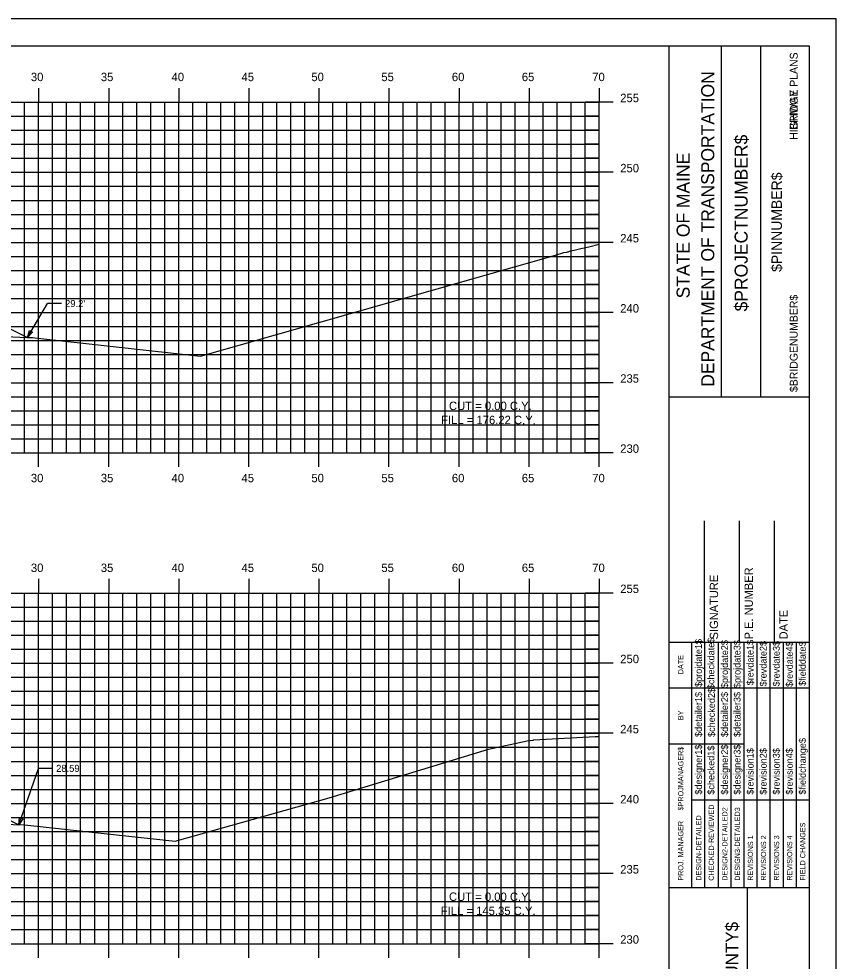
# Model space of a CAD drawing. Extents: x 1160718 to 1173142, y 616002 to 617630.
# Drawn here: x 1168216.9 to 1168275.2, y 616656.7 to 616723.9 of the extents above; entities that cross this region are included whole.
import ezdxf

# ---------------------------------------------------------------- set-up
doc = ezdxf.new("R2010")
doc.units = 0
for name, color, linetype in [('ANNOTATION', 7, 'Continuous'), ('BORDER', 7, 'Continuous'), ('BRIDGE_TITLE', 7, 'Continuous'), ('D_Roadway_SlopeLines', 7, 'Continuous'), ('H_V ANNOTATION', 7, 'Continuous'), ('HIGHWAY_TITLE', 7, 'Continuous'), ('MAJOR', 7, 'Continuous'), ('MINOR', 7, 'Continuous'), ('PLOT BOUNDARY', 7, 'Continuous'), ('S_Roadway_Centerline', 7, 'Continuous')]:
    doc.layers.add(name, color=color, linetype=linetype)

msp = doc.modelspace()

# ---------------------------------------------------------------- linework, layer by layer
at = {"layer": 'ANNOTATION'}
for p, q in [((1168217.545, 616701.158), (1168218.981, 616703.57)), ((1168219.981, 616703.57), (1168218.981, 616703.57)), ((1168216.931, 616666.408), (1168218.342, 616670.428)), ((1168219.342, 616670.428), (1168218.342, 616670.428))]:
    msp.add_line(p, q, dxfattribs=at)
for points in [[(1168217.908, 616701.523), (1168217.545, 616701.158), (1168217.694, 616701.651)], [(1168217.214, 616666.839), (1168216.931, 616666.408), (1168216.978, 616666.921)]]:
    msp.add_lwpolyline(points, close=True, dxfattribs=at)
at = {"layer": 'BORDER'}
for p, q in [((1168273.342, 616721.928), (1168113.342, 616721.928)), ((1168263.342, 616616.931), (1168263.342, 616721.931)), ((1168267.07, 616696.925), (1168267.07, 616721.925)), ((1168269.865, 616696.925), (1168269.865, 616721.925)), ((1168273.342, 616616.931), (1168273.342, 616721.931)), ((1168263.343, 616696.923), (1168273.342, 616696.923)), ((1168265.842, 616679.431), (1168265.842, 616688.079)), ((1168268.342, 616679.431), (1168268.342, 616688.079)), ((1168270.842, 616679.431), (1168270.842, 616688.079)), ((1168263.342, 616679.431), (1168273.342, 616679.431)), ((1168263.342, 616661.931), (1168273.342, 616661.931)), ((1168268.933, 616626.931), (1168268.933, 616661.931))]:
    msp.add_line(p, q, dxfattribs=at)
for points in [[(1168264.957, 616676.181), (1168264.957, 616679.431)], [(1168265.889, 616661.934), (1168265.889, 616679.431)], [(1168266.821, 616679.431), (1168266.821, 616661.934)], [(1168267.753, 616661.934), (1168267.753, 616679.431)], [(1168268.684, 616661.934), (1168268.684, 616679.431)], [(1168269.616, 616661.934), (1168269.616, 616679.431)], [(1168270.548, 616661.934), (1168270.548, 616679.431)], [(1168271.479, 616661.934), (1168271.479, 616679.431)], [(1168272.411, 616661.934), (1168272.411, 616679.431)], [(1168264.958, 616661.934), (1168264.958, 616678.725)], [(1168263.342, 616676.181), (1168273.342, 616676.181)], [(1168263.342, 616672.181), (1168264.958, 616672.181)], [(1168264.957, 616672.181), (1168268.683, 616672.181)], [(1168264.957, 616668.181), (1168273.342, 616668.181)]]:
    msp.add_lwpolyline(points, dxfattribs=at)
at = {"layer": 'D_Roadway_SlopeLines'}
for points in [[(1168208.342, 616705.76), (1168217.545, 616701.158)], [(1168208.342, 616670.703), (1168216.931, 616666.408)]]:
    msp.add_lwpolyline(points, dxfattribs=at)
at = {"layer": 'MAJOR'}
for p, q in [((1168218.342, 616718.93), (1168218.342, 616717.928)), ((1168223.342, 616718.93), (1168223.342, 616717.928)), ((1168228.342, 616718.93), (1168228.342, 616717.928)), ((1168233.342, 616718.93), (1168233.342, 616717.928)), ((1168238.342, 616718.93), (1168238.342, 616717.928)), ((1168243.342, 616718.93), (1168243.342, 616717.928)), ((1168248.342, 616718.93), (1168248.342, 616717.928)), ((1168253.342, 616718.93), (1168253.342, 616717.928)), ((1168258.342, 616718.93), (1168258.342, 616717.928)), ((1168118.342, 616717.928), (1168258.342, 616717.928)), ((1168118.342, 616717.928), (1168258.342, 616717.928)), ((1168218.342, 616692.928), (1168218.342, 616717.928)), ((1168223.342, 616692.928), (1168223.342, 616717.928)), ((1168228.342, 616692.928), (1168228.342, 616717.928)), ((1168233.342, 616692.928), (1168233.342, 616717.928)), ((1168238.342, 616692.928), (1168238.342, 616717.928)), ((1168243.342, 616692.928), (1168243.342, 616717.928)), ((1168248.342, 616692.928), (1168248.342, 616717.928)), ((1168253.342, 616692.928), (1168253.342, 616717.928)), ((1168259.344, 616717.928), (1168257.34, 616717.928)), ((1168258.342, 616692.928), (1168258.342, 616717.928)), ((1168258.342, 616692.928), (1168258.342, 616717.928)), ((1168118.342, 616712.928), (1168258.342, 616712.928)), ((1168259.344, 616712.928), (1168257.34, 616712.928)), ((1168118.342, 616707.928), (1168258.342, 616707.928)), ((1168259.344, 616707.928), (1168257.34, 616707.928)), ((1168118.342, 616702.928), (1168258.342, 616702.928)), ((1168259.344, 616702.928), (1168257.34, 616702.928)), ((1168118.342, 616697.928), (1168258.342, 616697.928)), ((1168259.344, 616697.928), (1168257.34, 616697.928)), ((1168118.342, 616692.928), (1168258.342, 616692.928)), ((1168118.342, 616692.928), (1168258.342, 616692.928)), ((1168218.342, 616691.926), (1168218.342, 616692.928)), ((1168223.342, 616691.926), (1168223.342, 616692.928)), ((1168228.342, 616691.926), (1168228.342, 616692.928)), ((1168233.342, 616691.926), (1168233.342, 616692.928)), ((1168238.342, 616691.926), (1168238.342, 616692.928)), ((1168243.342, 616691.926), (1168243.342, 616692.928)), ((1168248.342, 616691.926), (1168248.342, 616692.928)), ((1168253.342, 616691.926), (1168253.342, 616692.928)), ((1168259.344, 616692.928), (1168257.34, 616692.928)), ((1168258.342, 616691.926), (1168258.342, 616692.928)), ((1168218.342, 616683.93), (1168218.342, 616682.928)), ((1168223.342, 616683.93), (1168223.342, 616682.928)), ((1168228.342, 616683.93), (1168228.342, 616682.928)), ((1168233.342, 616683.93), (1168233.342, 616682.928)), ((1168238.342, 616683.93), (1168238.342, 616682.928)), ((1168243.342, 616683.93), (1168243.342, 616682.928)), ((1168248.342, 616683.93), (1168248.342, 616682.928)), ((1168253.342, 616683.93), (1168253.342, 616682.928)), ((1168258.342, 616683.93), (1168258.342, 616682.928)), ((1168118.342, 616682.928), (1168258.342, 616682.928)), ((1168118.342, 616682.928), (1168258.342, 616682.928)), ((1168218.342, 616657.928), (1168218.342, 616682.928)), ((1168223.342, 616657.928), (1168223.342, 616682.928)), ((1168228.342, 616657.928), (1168228.342, 616682.928)), ((1168233.342, 616657.928), (1168233.342, 616682.928)), ((1168238.342, 616657.928), (1168238.342, 616682.928)), ((1168243.342, 616657.928), (1168243.342, 616682.928)), ((1168248.342, 616657.928), (1168248.342, 616682.928)), ((1168253.342, 616657.928), (1168253.342, 616682.928)), ((1168259.344, 616682.928), (1168257.34, 616682.928)), ((1168258.342, 616657.928), (1168258.342, 616682.928)), ((1168258.342, 616657.928), (1168258.342, 616682.928)), ((1168118.342, 616677.928), (1168258.342, 616677.928)), ((1168259.344, 616677.928), (1168257.34, 616677.928)), ((1168118.342, 616672.928), (1168258.342, 616672.928)), ((1168259.344, 616672.928), (1168257.34, 616672.928)), ((1168118.342, 616667.928), (1168258.342, 616667.928)), ((1168259.344, 616667.928), (1168257.34, 616667.928)), ((1168118.342, 616662.928), (1168258.342, 616662.928)), ((1168259.344, 616662.928), (1168257.34, 616662.928)), ((1168118.342, 616657.928), (1168258.342, 616657.928)), ((1168118.342, 616657.928), (1168258.342, 616657.928)), ((1168218.342, 616656.926), (1168218.342, 616657.928)), ((1168223.342, 616656.926), (1168223.342, 616657.928)), ((1168228.342, 616656.926), (1168228.342, 616657.928)), ((1168233.342, 616656.926), (1168233.342, 616657.928)), ((1168238.342, 616656.926), (1168238.342, 616657.928)), ((1168243.342, 616656.926), (1168243.342, 616657.928)), ((1168248.342, 616656.926), (1168248.342, 616657.928)), ((1168253.342, 616656.926), (1168253.342, 616657.928)), ((1168259.344, 616657.928), (1168257.34, 616657.928)), ((1168258.342, 616656.926), (1168258.342, 616657.928))]:
    msp.add_line(p, q, dxfattribs=at)
at = {"layer": 'MINOR'}
for p, q in [((1168217.342, 616692.928), (1168217.342, 616717.928)), ((1168219.342, 616692.928), (1168219.342, 616717.928)), ((1168220.342, 616692.928), (1168220.342, 616717.928)), ((1168221.342, 616692.928), (1168221.342, 616717.928)), ((1168222.342, 616692.928), (1168222.342, 616717.928)), ((1168224.342, 616692.928), (1168224.342, 616717.928)), ((1168225.342, 616692.928), (1168225.342, 616717.928)), ((1168226.342, 616692.928), (1168226.342, 616717.928)), ((1168227.342, 616692.928), (1168227.342, 616717.928)), ((1168229.342, 616692.928), (1168229.342, 616717.928)), ((1168230.342, 616692.928), (1168230.342, 616717.928)), ((1168231.342, 616692.928), (1168231.342, 616717.928)), ((1168232.342, 616692.928), (1168232.342, 616717.928)), ((1168234.342, 616692.928), (1168234.342, 616717.928)), ((1168235.342, 616692.928), (1168235.342, 616717.928)), ((1168236.342, 616692.928), (1168236.342, 616717.928)), ((1168237.342, 616692.928), (1168237.342, 616717.928)), ((1168239.342, 616692.928), (1168239.342, 616717.928)), ((1168240.342, 616692.928), (1168240.342, 616717.928)), ((1168241.342, 616692.928), (1168241.342, 616717.928)), ((1168242.342, 616692.928), (1168242.342, 616717.928)), ((1168244.342, 616692.928), (1168244.342, 616717.928)), ((1168245.342, 616692.928), (1168245.342, 616717.928)), ((1168246.342, 616692.928), (1168246.342, 616717.928)), ((1168247.342, 616692.928), (1168247.342, 616717.928)), ((1168249.342, 616692.928), (1168249.342, 616717.928)), ((1168250.342, 616692.928), (1168250.342, 616717.928)), ((1168251.342, 616692.928), (1168251.342, 616717.928)), ((1168252.342, 616692.928), (1168252.342, 616717.928)), ((1168254.342, 616692.928), (1168254.342, 616717.928)), ((1168255.342, 616692.928), (1168255.342, 616717.928)), ((1168256.342, 616692.928), (1168256.342, 616717.928)), ((1168257.342, 616692.928), (1168257.342, 616717.928)), ((1168118.342, 616716.928), (1168258.342, 616716.928)), ((1168258.342, 616716.928), (1168257.34, 616716.928)), ((1168118.342, 616715.928), (1168258.342, 616715.928)), ((1168258.342, 616715.928), (1168257.34, 616715.928)), ((1168118.342, 616714.928), (1168258.342, 616714.928)), ((1168258.342, 616714.928), (1168257.34, 616714.928)), ((1168118.342, 616713.928), (1168258.342, 616713.928)), ((1168258.342, 616713.928), (1168257.34, 616713.928)), ((1168118.342, 616711.928), (1168258.342, 616711.928)), ((1168258.342, 616711.928), (1168257.34, 616711.928)), ((1168118.342, 616710.928), (1168258.342, 616710.928)), ((1168258.342, 616710.928), (1168257.34, 616710.928)), ((1168118.342, 616709.928), (1168258.342, 616709.928)), ((1168258.342, 616709.928), (1168257.34, 616709.928)), ((1168118.342, 616708.928), (1168258.342, 616708.928)), ((1168258.342, 616708.928), (1168257.34, 616708.928)), ((1168118.342, 616706.928), (1168258.342, 616706.928)), ((1168258.342, 616706.928), (1168257.34, 616706.928)), ((1168118.342, 616705.928), (1168258.342, 616705.928)), ((1168258.342, 616705.928), (1168257.34, 616705.928)), ((1168118.342, 616704.928), (1168258.342, 616704.928)), ((1168258.342, 616704.928), (1168257.34, 616704.928)), ((1168118.342, 616703.928), (1168258.342, 616703.928)), ((1168258.342, 616703.928), (1168257.34, 616703.928)), ((1168118.342, 616701.928), (1168258.342, 616701.928)), ((1168258.342, 616701.928), (1168257.34, 616701.928)), ((1168118.342, 616700.928), (1168258.342, 616700.928)), ((1168258.342, 616700.928), (1168257.34, 616700.928)), ((1168118.342, 616699.928), (1168258.342, 616699.928)), ((1168258.342, 616699.928), (1168257.34, 616699.928)), ((1168118.342, 616698.928), (1168258.342, 616698.928)), ((1168258.342, 616698.928), (1168257.34, 616698.928)), ((1168118.342, 616696.928), (1168258.342, 616696.928)), ((1168258.342, 616696.928), (1168257.34, 616696.928)), ((1168118.342, 616695.928), (1168258.342, 616695.928)), ((1168258.342, 616695.928), (1168257.34, 616695.928)), ((1168118.342, 616694.928), (1168258.342, 616694.928)), ((1168258.342, 616694.928), (1168257.34, 616694.928)), ((1168118.342, 616693.928), (1168258.342, 616693.928)), ((1168258.342, 616693.928), (1168257.34, 616693.928)), ((1168217.342, 616657.928), (1168217.342, 616682.928)), ((1168219.342, 616657.928), (1168219.342, 616682.928)), ((1168220.342, 616657.928), (1168220.342, 616682.928)), ((1168221.342, 616657.928), (1168221.342, 616682.928)), ((1168222.342, 616657.928), (1168222.342, 616682.928)), ((1168224.342, 616657.928), (1168224.342, 616682.928)), ((1168225.342, 616657.928), (1168225.342, 616682.928)), ((1168226.342, 616657.928), (1168226.342, 616682.928)), ((1168227.342, 616657.928), (1168227.342, 616682.928)), ((1168229.342, 616657.928), (1168229.342, 616682.928)), ((1168230.342, 616657.928), (1168230.342, 616682.928)), ((1168231.342, 616657.928), (1168231.342, 616682.928)), ((1168232.342, 616657.928), (1168232.342, 616682.928)), ((1168234.342, 616657.928), (1168234.342, 616682.928)), ((1168235.342, 616657.928), (1168235.342, 616682.928)), ((1168236.342, 616657.928), (1168236.342, 616682.928)), ((1168237.342, 616657.928), (1168237.342, 616682.928)), ((1168239.342, 616657.928), (1168239.342, 616682.928)), ((1168240.342, 616657.928), (1168240.342, 616682.928)), ((1168241.342, 616657.928), (1168241.342, 616682.928)), ((1168242.342, 616657.928), (1168242.342, 616682.928)), ((1168244.342, 616657.928), (1168244.342, 616682.928)), ((1168245.342, 616657.928), (1168245.342, 616682.928)), ((1168246.342, 616657.928), (1168246.342, 616682.928)), ((1168247.342, 616657.928), (1168247.342, 616682.928)), ((1168249.342, 616657.928), (1168249.342, 616682.928)), ((1168250.342, 616657.928), (1168250.342, 616682.928)), ((1168251.342, 616657.928), (1168251.342, 616682.928)), ((1168252.342, 616657.928), (1168252.342, 616682.928)), ((1168254.342, 616657.928), (1168254.342, 616682.928)), ((1168255.342, 616657.928), (1168255.342, 616682.928)), ((1168256.342, 616657.928), (1168256.342, 616682.928)), ((1168257.342, 616657.928), (1168257.342, 616682.928)), ((1168118.342, 616681.928), (1168258.342, 616681.928)), ((1168258.342, 616681.928), (1168257.34, 616681.928)), ((1168118.342, 616680.928), (1168258.342, 616680.928)), ((1168258.342, 616680.928), (1168257.34, 616680.928)), ((1168118.342, 616679.928), (1168258.342, 616679.928)), ((1168258.342, 616679.928), (1168257.34, 616679.928)), ((1168118.342, 616678.928), (1168258.342, 616678.928)), ((1168258.342, 616678.928), (1168257.34, 616678.928)), ((1168118.342, 616676.928), (1168258.342, 616676.928)), ((1168258.342, 616676.928), (1168257.34, 616676.928)), ((1168118.342, 616675.928), (1168258.342, 616675.928)), ((1168258.342, 616675.928), (1168257.34, 616675.928)), ((1168118.342, 616674.928), (1168258.342, 616674.928)), ((1168258.342, 616674.928), (1168257.34, 616674.928)), ((1168118.342, 616673.928), (1168258.342, 616673.928)), ((1168258.342, 616673.928), (1168257.34, 616673.928)), ((1168118.342, 616671.928), (1168258.342, 616671.928)), ((1168258.342, 616671.928), (1168257.34, 616671.928)), ((1168118.342, 616670.928), (1168258.342, 616670.928)), ((1168258.342, 616670.928), (1168257.34, 616670.928)), ((1168118.342, 616669.928), (1168258.342, 616669.928)), ((1168258.342, 616669.928), (1168257.34, 616669.928)), ((1168118.342, 616668.928), (1168258.342, 616668.928)), ((1168258.342, 616668.928), (1168257.34, 616668.928)), ((1168118.342, 616666.928), (1168258.342, 616666.928)), ((1168258.342, 616666.928), (1168257.34, 616666.928)), ((1168118.342, 616665.928), (1168258.342, 616665.928)), ((1168258.342, 616665.928), (1168257.34, 616665.928)), ((1168118.342, 616664.928), (1168258.342, 616664.928)), ((1168258.342, 616664.928), (1168257.34, 616664.928)), ((1168118.342, 616663.928), (1168258.342, 616663.928)), ((1168258.342, 616663.928), (1168257.34, 616663.928)), ((1168118.342, 616661.928), (1168258.342, 616661.928)), ((1168258.342, 616661.928), (1168257.34, 616661.928)), ((1168118.342, 616660.928), (1168258.342, 616660.928)), ((1168258.342, 616660.928), (1168257.34, 616660.928)), ((1168118.342, 616659.928), (1168258.342, 616659.928)), ((1168258.342, 616659.928), (1168257.34, 616659.928)), ((1168118.342, 616658.928), (1168258.342, 616658.928)), ((1168258.342, 616658.928), (1168257.34, 616658.928))]:
    msp.add_line(p, q, dxfattribs=at)
at = {"layer": 'PLOT BOUNDARY'}
msp.add_lwpolyline([(1168105.248, 616613.869), (1168275.248, 616613.869), (1168275.248, 616723.869), (1168105.248, 616723.869)], close=True, dxfattribs=at)
at = {"layer": 'S_Roadway_Centerline'}
for points in [[(1168209.955, 616701.5), (1168217.511, 616701.159), (1168217.905, 616701.147), (1168218.076, 616701.129), (1168229.884, 616699.825), (1168255.229, 616707.018), (1168255.829, 616707.202), (1168256.019, 616707.243), (1168256.021, 616707.243), (1168256.075, 616707.259), (1168256.116, 616707.266), (1168256.23, 616707.297), (1168256.4, 616707.341), (1168256.557, 616707.38), (1168257.026, 616707.483), (1168257.596, 616707.624), (1168258.342, 616707.804)], [(1168118.342, 616670.986), (1168130.612, 616670.558), (1168140.361, 616670.013), (1168144.163, 616669.811), (1168164.541, 616669.004), (1168184.956, 616667.903), (1168195.253, 616667.189), (1168204.218, 616666.784), (1168217.369, 616666.395), (1168223.021, 616665.786), (1168228.097, 616665.226), (1168239.076, 616668.338), (1168250.436, 616671.804), (1168253.197, 616672.394), (1168253.618, 616672.45), (1168253.622, 616672.451), (1168253.68, 616672.454), (1168258.057, 616672.707), (1168258.342, 616672.709)]]:
    msp.add_lwpolyline(points, dxfattribs=at)

# ---------------------------------------------------------------- texts
at = {"layer": 'ANNOTATION'}
for s, p in [("29.2'", (1168220.231, 616703.32)), ("28.59'", (1168219.592, 616670.178))]:
    msp.add_text(s, height=0.5, dxfattribs=at).set_placement(p)
for s, p in [('CUT = 0.00 C.Y.', (1168247.621, 616695.978)), ('FILL = 176.22 C.Y.', (1168247.063, 616694.977)), ('CUT = 0.00 C.Y.', (1168247.621, 616660.978)), ('FILL = 145.35 C.Y.', (1168247.042, 616659.977))]:
    msp.add_text(s, height=0.6, rotation=359.92408, dxfattribs=at).set_placement(p)
at = {"layer": 'BORDER'}
for s, height, p in [('DEPARTMENT OF TRANSPORTATION', 0.93176, (1168266.549, 616697.634)), ('$PROJECTNUMBER$', 0.93176, (1168268.934, 616703.008)), ('STATE OF MAINE', 0.93176, (1168264.797, 616703.94)), ('$PINNUMBER$', 0.74527, (1168271.379, 616705.825)), ('SIGNATURE', 0.5906, (1168266.822, 616679.624)), ('P.E. NUMBER', 0.59055, (1168269.303, 616679.624)), ('DATE', 0.5906, (1168271.783, 616679.624)), ('$projdate1$', 0.48455, (1168265.665, 616676.232)), ('$checkdate$', 0.48455, (1168266.559, 616676.074)), ('$projdate2$', 0.48455, (1168267.528, 616676.153)), ('$projdate3$', 0.48455, (1168268.423, 616676.153)), ('$revdate1$', 0.4845, (1168269.354, 616676.35)), ('$revdate2$', 0.4845, (1168270.286, 616676.271)), ('$revdate3$', 0.4845, (1168271.218, 616676.271)), ('$revdate4$', 0.4845, (1168272.149, 616676.232)), ('$fielddate$', 0.48455, (1168273.081, 616676.31)), ('DATE', 0.3714, (1168264.346, 616677.137)), ('$checked2$', 0.4845, (1168266.596, 616672.667)), ('$detailer1$', 0.48455, (1168265.665, 616672.667)), ('$detailer2$', 0.48455, (1168267.528, 616672.667)), ('$detailer3$', 0.48455, (1168268.423, 616672.667)), ('BY', 0.3714, (1168264.346, 616673.866)), ('$designer1$', 0.48455, (1168265.665, 616668.555)), ('$checked1$', 0.4845, (1168266.559, 616668.555)), ('$designer2$', 0.48455, (1168267.528, 616668.555)), ('$designer3$', 0.48455, (1168268.423, 616668.555)), ('$fieldchange$', 0.48455, (1168273.081, 616668.555)), ('$PROJMANAGER$', 0.37275, (1168264.346, 616667.426)), ('$revision1$', 0.48455, (1168269.354, 616668.555)), ('$revision2$', 0.48455, (1168270.286, 616668.555)), ('$revision3$', 0.48455, (1168271.218, 616668.555)), ('$revision4$', 0.48455, (1168272.149, 616668.555)), ('CHECKED-REVIEWED', 0.37275, (1168266.523, 616662.419)), ('DESIGN2-DETAILED2', 0.37275, (1168267.492, 616662.419)), ('DESIGN3-DETAILED3', 0.37275, (1168268.386, 616662.419)), ('DESIGN-DETAILED', 0.37275, (1168265.628, 616662.419)), ('PROJ. MANAGER', 0.37275, (1168264.346, 616662.419)), ('FIELD CHANGES', 0.37275, (1168273.045, 616662.419)), ('REVISIONS 1', 0.37275, (1168269.318, 616662.419)), ('REVISIONS 2', 0.37275, (1168270.25, 616662.419)), ('REVISIONS 3', 0.37275, (1168271.181, 616662.419)), ('REVISIONS 4', 0.37275, (1168272.113, 616662.419))]:
    msp.add_text(s, height=height, rotation=90, dxfattribs=at).set_placement(p)
at = {"layer": 'BRIDGE_TITLE'}
for s, height, p in [('BRIDGE PLANS', 0.55901, (1168272.5, 616715.953)), ('$BRIDGENUMBER$', 0.55901, (1168272.5, 616697.259)), ('$COUNTY$', 0.9072, (1168268.262, 616653.011))]:
    msp.add_text(s, height=height, rotation=90, dxfattribs=at).set_placement(p)
at = {"layer": 'H_V ANNOTATION'}
for s, p in [('30', (1168217.79, 616719.428)), ('35', (1168222.782, 616719.428)), ('40', (1168227.828, 616719.428)), ('45', (1168232.82, 616719.428)), ('50', (1168237.806, 616719.428)), ('55', (1168242.798, 616719.428)), ('60', (1168247.828, 616719.428)), ('65', (1168252.82, 616719.428)), ('70', (1168257.844, 616719.428)), ('255', (1168259.842, 616717.928)), ('250', (1168259.842, 616712.928)), ('245', (1168259.842, 616707.928)), ('240', (1168259.842, 616702.928)), ('235', (1168259.842, 616697.928)), ('230', (1168259.842, 616692.928)), ('30', (1168217.79, 616690.828)), ('35', (1168222.782, 616690.828)), ('40', (1168227.828, 616690.828)), ('45', (1168232.82, 616690.828)), ('50', (1168237.806, 616690.828)), ('55', (1168242.798, 616690.828)), ('60', (1168247.828, 616690.828)), ('65', (1168252.82, 616690.828)), ('70', (1168257.844, 616690.828)), ('30', (1168217.79, 616684.428)), ('35', (1168222.782, 616684.428)), ('40', (1168227.828, 616684.428)), ('45', (1168232.82, 616684.428)), ('50', (1168237.806, 616684.428)), ('55', (1168242.798, 616684.428)), ('60', (1168247.828, 616684.428)), ('65', (1168252.82, 616684.428)), ('70', (1168257.844, 616684.428)), ('255', (1168259.842, 616682.928)), ('250', (1168259.842, 616677.928)), ('245', (1168259.842, 616672.928)), ('240', (1168259.842, 616667.928)), ('235', (1168259.842, 616662.928)), ('230', (1168259.842, 616657.928))]:
    msp.add_text(s, height=0.6, dxfattribs=at).set_placement(p)
at = {"layer": 'HIGHWAY_TITLE'}
msp.add_text('HIGHWAY PLANS', height=0.55901, rotation=90, dxfattribs=at).set_placement((1168272.5, 616715.244))

doc.saveas('drawing.dxf')
